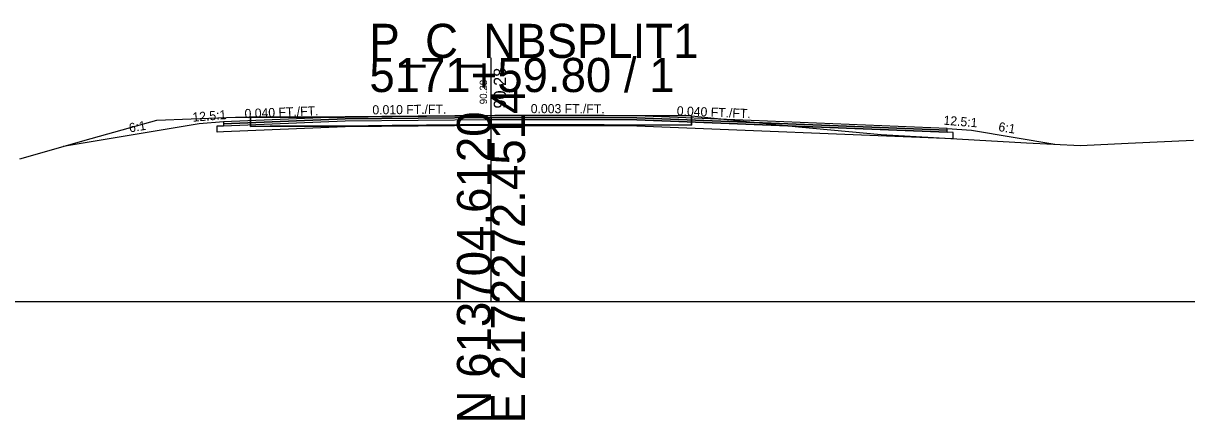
# Model space of a CAD drawing. Extents: x -26 to 1303, y -3010 to 12038.
# Drawn here: x 111.5 to 207.2, y -9.7 to 22.8 of the extents above; entities that cross this region are included whole.
import ezdxf

# ---------------------------------------------------------------- set-up
doc = ezdxf.new("R2010")
doc.units = 0
for name, color, linetype in [('RD_GPK_XS_Cell', 7, 'Continuous'), ('RD_XS_Base', 7, 'Continuous'), ('RD_XS_ExGround', 7, 'Continuous'), ('RD_XS_ExPaveRet', 7, 'Continuous'), ('RD_XS_Greenside', 7, 'Continuous'), ('RD_XS_Pave', 7, 'Continuous'), ('RD_XS_PaveOvlay_CP', 7, 'Continuous'), ('RD_XS_TieSlope', 7, 'Continuous'), ('RD_XS_TX_Elev_EX', 7, 'Continuous'), ('RD_XS_TX_Elev_PR', 7, 'Continuous'), ('RD_XS_TX_ShdSlope', 7, 'Continuous'), ('RD_XS_TX_Slope', 7, 'Continuous')]:
    doc.layers.add(name, color=color, linetype=linetype)

msp = doc.modelspace()

# ---------------------------------------------------------------- linework, layer by layer
at = {"layer": 'RD_GPK_XS_Cell'}
for p, q in [((150, 0), (150, 20)), ((0, 0), (150, 0)), ((150, 0), (300, 0))]:
    msp.add_line(p, q, dxfattribs=at)
at = {"layer": 'RD_XS_Base'}
for p, q in [((127.5, 14.419), (128, 14.439)), ((127.5, 13.919), (127.5, 14.419)), ((127.5, 14.419), (127.5, 14.419)), ((128, 14.439), (138, 14.838)), ((128, 14.439), (128, 14.439)), ((138, 14.838), (150, 14.957)), ((138, 14.838), (138, 14.838)), ((150, 14.457), (138, 14.338)), ((150, 14.957), (150, 15.116)), ((150, 15.116), (150, 14.457)), ((150, 14.957), (150, 14.957)), ((150, 14.957), (150, 14.957)), ((162, 14.921), (150, 14.957)), ((150, 14.957), (150, 14.457)), ((150, 14.457), (150, 14.457)), ((150, 14.457), (150, 14.457)), ((150, 14.457), (162, 14.421)), ((150, 14.457), (150, 14.457)), ((187.505, 13.901), (162, 14.921)), ((162, 14.421), (188.005, 13.381)), ((164, 14.841), (164, 14.841)), ((128, 13.939), (127.5, 13.919)), ((127.5, 13.919), (127.5, 13.919)), ((127.5, 13.919), (127.5, 13.919)), ((138, 14.338), (128, 13.939)), ((128, 13.939), (128, 13.939)), ((138, 14.338), (138, 14.338)), ((164, 14.341), (164, 14.341)), ((188.005, 13.881), (187.505, 13.901)), ((187.505, 13.901), (187.505, 13.901)), ((188.005, 13.381), (188.005, 13.881)), ((188.005, 13.881), (188.005, 13.881))]:
    msp.add_line(p, q, dxfattribs=at)
at = {"layer": 'RD_XS_ExGround'}
msp.add_lwpolyline([(111.252, 11.728), (117.133, 13.382), (120.37, 14.279), (122.533, 14.892), (125.356, 14.996), (129.004, 15.128), (130.219, 15.125), (131.851, 15.136), (137.968, 15.151), (141.878, 15.203), (150.316, 15.278), (159.315, 15.265), (166.478, 15.234), (175.282, 14.347), (182.086, 13.72), (194.018, 13.041), (198.467, 12.809), (202.387, 13.004), (207.743, 13.249)], dxfattribs=at)
at = {"layer": 'RD_XS_ExPaveRet'}
for p, q in [((150.316, 15.278), (141.878, 15.203)), ((166.478, 15.234), (166.478, 15.235))]:
    msp.add_line(p, q, dxfattribs=at)
for points in [[(166.478, 15.234), (166.478, 14.484), (166.478, 14.484), (166.478, 14.484), (166.478, 14.484), (159.315, 14.515), (159.315, 14.515), (150.316, 14.528), (141.878, 14.453), (141.878, 14.453), (137.968, 14.401), (137.968, 14.401), (137.968, 14.401), (131.851, 14.386), (131.851, 14.386), (130.219, 14.375), (130.219, 14.375), (130.219, 15.125), (131.851, 15.136), (131.851, 15.136), (137.968, 15.151), (137.968, 15.151), (137.968, 15.151), (141.878, 15.203), (141.878, 15.203), (150.316, 15.278), (159.315, 15.265), (159.315, 15.265), (166.478, 15.235), (166.478, 15.235), (166.478, 15.234)], [(141.878, 15.203), (137.968, 15.151), (131.851, 15.136), (130.219, 15.125), (130.219, 14.375), (131.851, 14.386), (137.968, 14.401), (141.878, 14.453), (150.316, 14.528), (159.315, 14.515), (166.478, 14.484), (166.478, 14.484), (166.478, 15.234)], [(166.478, 15.235), (159.315, 15.265), (150.316, 15.278)]]:
    msp.add_lwpolyline(points, dxfattribs=at)
at = {"layer": 'RD_XS_Greenside'}
for p, q in [((126, 14.597), (114.833, 12.735)), ((189.505, 14.059), (196.342, 12.92))]:
    msp.add_line(p, q, dxfattribs=at)
at = {"layer": 'RD_XS_Pave'}
for p, q in [((138, 15.157), (128, 14.757)), ((138, 14.997), (128, 14.598)), ((128, 14.598), (138, 14.997)), ((128, 14.439), (138, 14.838)), ((128, 14.757), (128, 14.757)), ((128, 14.757), (128, 14.598)), ((128, 14.598), (128, 14.598)), ((128, 14.598), (128, 14.439)), ((128, 14.598), (128, 14.598)), ((128, 14.598), (128, 14.598)), ((128, 14.439), (128, 14.439)), ((128, 14.439), (128, 14.439)), ((150, 15.275), (138, 15.157)), ((138, 15.157), (138, 15.157)), ((150, 15.116), (138, 14.997)), ((138, 14.997), (150, 15.116)), ((138, 14.997), (138, 14.997)), ((138, 14.997), (138, 14.997)), ((138, 14.838), (150, 14.957)), ((138, 14.838), (138, 14.838)), ((162, 15.239), (150, 15.275)), ((150, 15.275), (150, 15.275)), ((162, 15.08), (150, 15.116)), ((150, 15.116), (150, 15.116)), ((150, 15.116), (150, 14.957)), ((150, 14.957), (150, 15.116)), ((150, 15.116), (150, 15.116)), ((150, 15.116), (162, 15.08)), ((150, 14.957), (150, 14.957)), ((150, 14.957), (150, 14.957)), ((150, 14.957), (162, 14.921)), ((150, 14.957), (150, 14.957)), ((187.505, 14.219), (162, 15.239)), ((187.505, 14.06), (162, 15.08)), ((162, 15.08), (187.505, 14.06)), ((162, 14.921), (187.505, 13.901)), ((164, 15.159), (164, 15.159)), ((164, 15), (164, 15)), ((164, 15), (164, 15)), ((164, 14.841), (164, 14.841)), ((187.505, 14.06), (187.505, 14.219)), ((187.505, 14.219), (187.505, 14.219)), ((187.505, 13.901), (187.505, 14.06)), ((187.505, 14.06), (187.505, 14.06))]:
    msp.add_line(p, q, dxfattribs=at)
at = {"layer": 'RD_XS_PaveOvlay_CP'}
for p, q in [((138, 15.157), (128, 14.757)), ((128, 14.757), (128, 14.757)), ((150, 15.275), (138, 15.157)), ((138, 15.157), (138, 15.157)), ((162, 15.239), (150, 15.275)), ((150, 15.275), (150, 15.275)), ((187.505, 14.219), (162, 15.239)), ((164, 15.159), (164, 15.159))]:
    msp.add_line(p, q, dxfattribs=at)
at = {"layer": 'RD_XS_TieSlope'}
for p, q in [((128, 14.757), (126, 14.597)), ((187.505, 14.219), (189.505, 14.059))]:
    msp.add_line(p, q, dxfattribs=at)

# ---------------------------------------------------------------- texts
at = {"layer": 'RD_GPK_XS_Cell'}
for s, p in [('P_C_NBSPLIT1', (140, 20)), ('5171+59.80 / 1', (140, 17.2))]:
    msp.add_text(s, height=2.8, dxfattribs=at).set_placement(p)
for s, p in [('E 2172272.4514', (152.8, -10)), ('N 613704.6120', (150, -10))]:
    msp.add_text(s, height=2.8, rotation=90, dxfattribs=at).set_placement(p)
at = {"layer": 'RD_XS_TX_Elev_EX'}
msp.add_text('90.28', height=0.6, rotation=90, dxfattribs=at).set_placement((149.675, 16.194))
at = {"layer": 'RD_XS_TX_Elev_PR'}
msp.add_text('90.28', height=1, rotation=90, dxfattribs=at).set_placement((151.223, 15.844))
at = {"layer": 'RD_XS_TX_ShdSlope'}
for rotation, p in [(4.57392, (125.487, 14.761)), (355.42608, (187.177, 14.524))]:
    msp.add_text('12.5:1', height=0.75, rotation=rotation, dxfattribs=at).set_placement(p)
at = {"layer": 'RD_XS_TX_Slope'}
for s, rotation, p in [('0.040 FT./FT.', 2.29061, (129.755, 15.052)), ('0.010 FT./FT.', 0.56721, (140.25, 15.364)), ('0.003 FT./FT.', 359.82811, (153.264, 15.467)), ('0.040 FT./FT.', 357.70939, (165.262, 15.294)), ('6:1', 9.46232, (120.303, 13.88)), ('6:1', 350.53768, (191.67, 14.008))]:
    msp.add_text(s, height=0.75, rotation=rotation, dxfattribs=at).set_placement(p)

doc.saveas('drawing.dxf')
